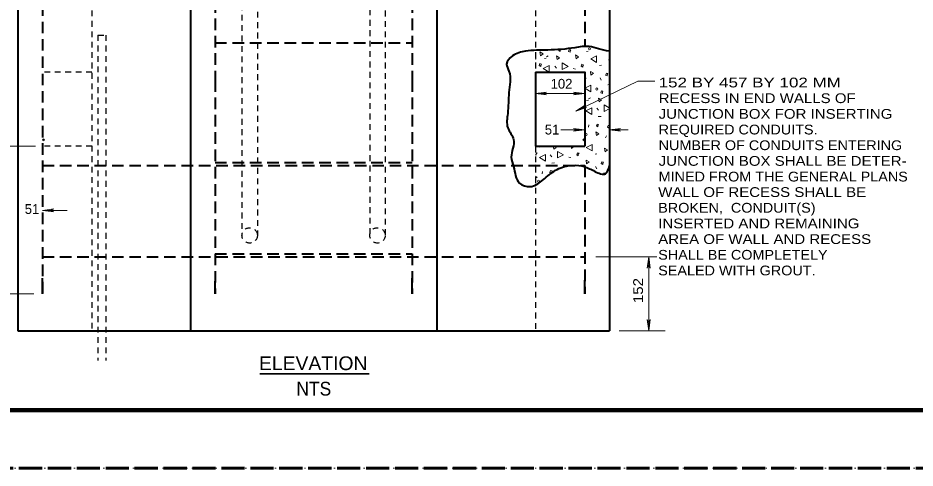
# Model space of a CAD drawing. Extents: x 312583 to 312854, y 144419 to 144597.
# Drawn here: x 312622.6 to 312692.4, y 144418.6 to 144453.6 of the extents above; entities that cross this region are included whole.
import ezdxf
from ezdxf.enums import TextEntityAlignment as Align

# ---------------------------------------------------------------- set-up
doc = ezdxf.new("R2010")
doc.units = 0
doc.header["$LTSCALE"] = 0.3
doc.header["$PDMODE"] = 32
doc.header["$PDSIZE"] = 0.15
for name, pattern in [('DOTTED', [1.5, 0.3, -1.2]), ('LONG_DASHED', [7.5, 6, -1.5]), ('MEDIUM_DASHED', [4.5, 3, -1.5]), ('SHORT_DASHED', [2.7, 1.5, -1.2])]:
    doc.linetypes.add(name, pattern=pattern)
doc.layers.add('1', color=7, linetype='Continuous', lineweight=13)
doc.layers.add('63', color=7, linetype='DOTTED', lineweight=13)

msp = doc.modelspace()

# ---------------------------------------------------------------- linework, layer by layer
at = {"layer": '1', "lineweight": 40}
for p, q in [((312622.6224, 144471.9161), (312622.6224, 144429.2664)), ((312636.039, 144471.9161), (312636.039, 144448.7628)), ((312655.2057, 144471.9161), (312655.2057, 144448.7628)), ((312668.6224, 144471.9161), (312668.6224, 144429.2664)), ((312662.8724, 144449.3914), (312662.8724, 144443.6414)), ((312636.039, 144448.7628), (312636.039, 144429.2664)), ((312655.2057, 144448.7628), (312655.2057, 144429.2664)), ((312662.8724, 144443.6414), (312666.7057, 144443.6414)), ((312624.539, 144432.1414), (312624.539, 144433.3604)), ((312637.9557, 144432.1414), (312637.9557, 144433.1381)), ((312653.289, 144432.1414), (312653.289, 144433.3604)), ((312666.7057, 144432.1414), (312666.7057, 144433.2148)), ((312622.6224, 144429.2664), (312668.6224, 144429.2664))]:
    msp.add_line(p, q, dxfattribs=at)
at = {"layer": '1', "linetype": 'SHORT_DASHED', "lineweight": 25}
for p, q in [((312628.3724, 144471.1954), (312628.3724, 144429.2664)), ((312662.8724, 144471.1954), (312662.8724, 144449.3914)), ((312640.0487, 144465.1924), (312640.0487, 144436.6878)), ((312641.2447, 144465.4224), (312641.2447, 144436.6878)), ((312649.9924, 144464.7938), (312649.9924, 144436.6878)), ((312651.1884, 144464.7094), (312651.1884, 144436.6878)), ((312628.8477, 144452.2664), (312628.8477, 144426.9664)), ((312628.8477, 144452.2664), (312629.4457, 144452.2664)), ((312629.4457, 144452.2664), (312629.4457, 144426.9664)), ((312628.3724, 144449.3914), (312624.539, 144449.3914)), ((312628.3724, 144443.6414), (312624.539, 144443.6414)), ((312662.8724, 144443.6414), (312662.8724, 144429.2664))]:
    msp.add_line(p, q, dxfattribs=at)
at = {"layer": '1', "linetype": 'MEDIUM_DASHED', "lineweight": 40}
for p, q in [((312624.539, 144469.5164), (312624.539, 144432.1414)), ((312637.9557, 144469.7541), (312637.9557, 144448.7628)), ((312653.289, 144469.7541), (312653.289, 144448.7628)), ((312666.7057, 144469.5164), (312666.7057, 144451.3541)), ((312637.9557, 144451.6838), (312653.289, 144451.6838)), ((312637.9557, 144448.7628), (312637.9557, 144432.1414)), ((312653.289, 144448.7628), (312653.289, 144432.1414)), ((312637.9557, 144442.3688), (312653.289, 144442.3688)), ((312624.539, 144442.1311), (312666.7057, 144442.1311)), ((312666.7057, 144442.1311), (312666.7057, 144432.1414)), ((312637.9557, 144435.2541), (312653.289, 144435.2541)), ((312624.539, 144435.0164), (312666.7057, 144435.0164))]:
    msp.add_line(p, q, dxfattribs=at)
at = {"layer": '1'}
for p, q in [((312663.7387, 144450.5874), (312663.869, 144450.6564)), ((312666.836, 144451.0091), (312666.9817, 144451.0168)), ((312662.857, 144450.4188), (312662.8954, 144450.3958)), ((312663.57, 144450.4571), (312663.7157, 144450.4878)), ((312664.375, 144449.8591), (312664.4977, 144449.6981)), ((312667.8557, 144449.9128), (312668.0014, 144449.9204)), ((312665.8087, 144449.6674), (312665.9774, 144449.6214)), ((312666.8284, 144448.9544), (312666.721, 144448.8701)), ((312667.894, 144448.9391), (312667.9784, 144448.7628)), ((312662.8724, 144447.7354), (312663.7387, 144447.8428)), ((312663.7387, 144447.8428), (312663.4627, 144447.7354)), ((312665.8394, 144447.8428), (312666.1154, 144447.7354)), ((312666.7057, 144447.7354), (312665.8394, 144447.8428)), ((312668.4997, 144448.4101), (312668.6147, 144448.4408)), ((312662.8724, 144447.7354), (312666.7057, 144447.7354)), ((312662.8724, 144447.7354), (312663.7387, 144447.6281)), ((312663.7387, 144447.6281), (312663.4627, 144447.7354)), ((312665.8394, 144447.6281), (312666.1154, 144447.7354)), ((312666.7057, 144447.7354), (312665.8394, 144447.6281)), ((312666.8437, 144447.1834), (312666.9894, 144447.2141)), ((312667.0124, 144447.3138), (312667.1427, 144447.3904)), ((312666.0234, 144446.3478), (312666.7517, 144446.8231)), ((312666.0234, 144446.3478), (312666.8514, 144446.6314)), ((312666.7517, 144446.8231), (312666.5524, 144446.6008)), ((312666.8514, 144446.6314), (312666.5524, 144446.6008)), ((312667.6487, 144446.5854), (312667.7714, 144446.4321)), ((312668.6147, 144446.6008), (312668.216, 144446.8461)), ((312667.7637, 144445.9338), (312667.9784, 144445.9414)), ((312665.8394, 144445.0138), (312666.1154, 144444.9064)), ((312666.7057, 144444.9064), (312665.8394, 144445.0138)), ((312667.0047, 144445.0981), (312667.0277, 144445.2898)), ((312668.607, 144445.1364), (312668.6147, 144445.1594)), ((312668.6224, 144444.9064), (312669.4887, 144445.0138)), ((312669.4887, 144445.0138), (312669.2127, 144444.9064)), ((312664.8552, 144444.9064), (312666.7057, 144444.9064)), ((312665.8394, 144444.7991), (312666.1154, 144444.9064)), ((312666.7057, 144444.9064), (312665.8394, 144444.7991)), ((312668.4, 144444.4388), (312668.3234, 144444.2701)), ((312668.6224, 144444.9064), (312670.079, 144444.9064)), ((312668.6224, 144444.9064), (312669.4887, 144444.7991)), ((312669.4887, 144444.7991), (312669.2127, 144444.9064)), ((312623.987, 144443.6414), (312617.434, 144443.6414)), ((312663.225, 144443.5648), (312663.3707, 144443.5954)), ((312664.2524, 144443.6414), (312664.2907, 144443.3884)), ((312665.6554, 144443.6261), (312665.6784, 144443.4498)), ((312664.03, 144442.9668), (312664.1527, 144442.8134)), ((312667.5107, 144443.0204), (312667.6564, 144443.0358)), ((312664.145, 144442.3151), (312664.3597, 144442.3228)), ((312665.4637, 144442.7751), (312665.6324, 144442.7368)), ((312663.386, 144441.4871), (312663.409, 144441.6711)), ((312664.122, 144441.5714), (312664.122, 144441.6174)), ((312667.549, 144442.0468), (312667.641, 144441.8781)), ((312668.1547, 144441.5178), (312668.3004, 144441.5638)), ((312624.5383, 144438.6357), (312625.4047, 144438.743)), ((312625.4047, 144438.743), (312625.1287, 144438.6357)), ((312624.5383, 144438.6357), (312626.4519, 144438.6357)), ((312624.5383, 144438.6357), (312625.4047, 144438.5283)), ((312625.4047, 144438.5283), (312625.1287, 144438.6357)), ((312667.572, 144435.0164), (312672.3254, 144435.0164)), ((312671.6814, 144435.0164), (312671.574, 144434.1501)), ((312671.6814, 144429.2664), (312671.6814, 144435.0164)), ((312671.6814, 144435.0164), (312671.7887, 144434.1501)), ((312671.574, 144434.1501), (312671.6814, 144434.4261)), ((312671.7887, 144434.1501), (312671.6814, 144434.4261)), ((312623.8567, 144432.1414), (312619.5864, 144432.1414)), ((312671.574, 144430.1328), (312671.6814, 144429.8568)), ((312671.6814, 144429.2664), (312671.574, 144430.1328)), ((312671.7887, 144430.1328), (312671.6814, 144429.8568)), ((312671.6814, 144429.2664), (312671.7887, 144430.1328)), ((312669.389, 144429.2664), (312672.9617, 144429.2664))]:
    msp.add_line(p, q, dxfattribs=at)
at = {"layer": '1', "lineweight": 35}
msp.add_line((312641.4323, 144425.9161), (312649.9363, 144425.9161), dxfattribs=at)
at = {"layer": '1', "lineweight": 158}
msp.add_line((312616.5, 144423.0846), (312849, 144423.0846), dxfattribs=at)
at = {"layer": '1', "linetype": 'LONG_DASHED', "lineweight": 60}
msp.add_line((312851.75, 144418.5846), (312583.526, 144418.5846), dxfattribs=at)
at = {"layer": '1'}
for points in [[(312662.8954, 144450.3958), (312662.8954, 144450.9094), (312662.857, 144450.8941)], [(312664.7277, 144451.1778), (312664.6817, 144451.0628), (312664.8044, 144450.9938), (312664.8044, 144451.1011)], [(312664.8044, 144451.1011), (312664.8504, 144451.1778), (312664.8197, 144451.1931)], [(312668.6224, 144450.3498), (312668.5917, 144450.3651), (312668.6224, 144450.1504)], [(312672.1644, 144448.6938), (312670.8304, 144448.6938), (312666.0234, 144446.3478)], [(312668.216, 144446.8461), (312668.216, 144446.3324), (312668.6147, 144446.5318)], [(312668.6147, 144445.2284), (312668.538, 144445.2514), (312668.4767, 144445.1058), (312668.607, 144445.0291), (312668.607, 144445.1364)], [(312664.2907, 144443.3884), (312664.4824, 144443.5341), (312664.306, 144443.6414)], [(312665.6784, 144443.4498), (312665.87, 144443.6031), (312665.8317, 144443.6261)], [(312662.9414, 144443.0434), (312662.995, 144443.1201), (312662.8724, 144443.1584), (312662.8724, 144443.1508)], [(312662.8724, 144442.9744), (312662.9414, 144442.9361), (312662.9414, 144443.0434)], [(312662.8724, 144442.1388), (312662.8954, 144442.1541), (312662.8724, 144442.1694)], [(312664.122, 144441.6174), (312664.168, 144441.7018), (312664.0454, 144441.7401), (312663.9917, 144441.5868), (312664.076, 144441.5408)], [(312662.8724, 144441.1344), (312663.0104, 144441.2034), (312662.8724, 144441.2878)]]:
    msp.add_lwpolyline(points, dxfattribs=at)
for points in [[(312663.271, 144450.6718), (312663.4627, 144450.8251), (312663.225, 144450.9631)], [(312664.5514, 144450.3651), (312664.743, 144450.5108), (312664.513, 144450.6488)], [(312665.571, 144451.0474), (312665.617, 144451.1241), (312665.502, 144451.1624), (312665.4407, 144451.0091), (312665.571, 144450.9401)], [(312666.031, 144450.4341), (312666.2227, 144450.5874), (312665.985, 144450.7254)], [(312667.6334, 144450.1428), (312667.6334, 144450.6641), (312667.1734, 144450.4264)], [(312663.2864, 144449.9281), (312663.3324, 144450.0124), (312663.2174, 144450.0508), (312663.156, 144449.8974), (312663.2864, 144449.8284)], [(312663.9457, 144449.3991), (312663.9457, 144449.9128), (312663.478, 144449.6828)], [(312664.9424, 144450.1198), (312664.9424, 144449.6061), (312665.41, 144449.8361)], [(312666.5524, 144449.8898), (312666.5984, 144449.9664), (312666.4834, 144450.0048), (312666.4297, 144449.8514), (312666.5524, 144449.7824)], [(312667.1887, 144449.1538), (312667.388, 144449.3071), (312667.1504, 144449.4451)], [(312668.4614, 144449.1998), (312668.5074, 144449.2764), (312668.3924, 144449.3148), (312668.331, 144449.1614), (312668.4614, 144449.0924)], [(312667.181, 144447.8581), (312667.181, 144448.3718), (312666.7134, 144448.1418)], [(312668.078, 144447.8274), (312668.124, 144447.9041), (312668.009, 144447.9424), (312667.9554, 144447.7891), (312668.078, 144447.7201)], [(312667.825, 144447.0914), (312668.0167, 144447.2371), (312667.779, 144447.3751)], [(312667.2654, 144446.0871), (312667.2654, 144446.6084), (312666.7977, 144446.3708)], [(312667.733, 144445.2361), (312667.779, 144445.3204), (312667.664, 144445.3511), (312667.6104, 144445.2054), (312667.733, 144445.1288)], [(312667.618, 144444.4541), (312667.8097, 144444.5998), (312667.5797, 144444.7378)], [(312667.296, 144443.2581), (312667.296, 144443.7718), (312666.8284, 144443.5341)], [(312663.6467, 144442.4761), (312663.6467, 144442.9898), (312663.179, 144442.7521)], [(312664.5974, 144443.2274), (312664.5974, 144442.7138), (312665.065, 144442.9438)], [(312666.2074, 144442.9974), (312666.261, 144443.0818), (312666.1384, 144443.1124), (312666.0847, 144442.9591), (312666.2074, 144442.8901)], [(312668.285, 144443.1891), (312668.4767, 144443.3348), (312668.2467, 144443.4804)], [(312666.8514, 144442.2691), (312667.043, 144442.4148), (312666.8054, 144442.5528)], [(312668.1164, 144442.3074), (312668.1624, 144442.3918), (312668.0474, 144442.4224), (312667.986, 144442.2768), (312668.1164, 144442.2001)]]:
    msp.add_lwpolyline(points, close=True, dxfattribs=at)
at = {"layer": '1', "lineweight": 40}
msp.add_lwpolyline([(312662.8724, 144449.3914), (312666.7057, 144449.3914), (312666.7057, 144443.6414)], dxfattribs=at)
at = {"layer": '1'}
for centre, radius in [((312667.0746, 144451.2129), 0.0784), ((312667.6475, 144448.0709), 0.0865), ((312666.8061, 144444.5305), 0.0784), ((312663.1131, 144440.9066), 0.0784)]:
    msp.add_circle(centre, radius, dxfattribs=at)
at = {"layer": '1', "linetype": 'SHORT_DASHED', "lineweight": 25}
for centre in [(312640.6467, 144436.6897), (312650.5904, 144436.6897)]:
    msp.add_circle(centre, 0.599, dxfattribs=at)
at = {"layer": '1', "lineweight": 40}
msp.add_spline([(312668.6224, 144451.0168), (312667.7714, 144451.2008), (312667.043, 144451.3848), (312665.939, 144451.2928), (312663.8307, 144451.1088), (312662.0904, 144451.0168), (312661.086, 144450.6488), (312660.626, 144450.0124), (312660.81, 144449.4604), (312660.81, 144447.8121), (312660.718, 144446.1638), (312660.718, 144445.0598), (312661.178, 144444.1474), (312660.994, 144442.7751), (312661.178, 144442.0391), (312661.6304, 144440.7588), (312662.4584, 144440.4828), (312663.3784, 144440.9351), (312664.2907, 144441.6711), (312664.8427, 144441.9471), (312666.675, 144442.0391), (312667.4954, 144441.6711), (312668.3234, 144441.4871), (312668.6224, 144442.1311)], degree=3, dxfattribs=at)
at = {"layer": '1'}
for p in [(312624.6004, 144444.1244), (312666.6367, 144444.1244)]:
    msp.add_point(p, dxfattribs=at)
at = {"layer": '63'}
msp.add_lwpolyline([(312601.2, 144418.5846), (312853.5, 144418.5846), (312853.5, 144596.7846)], dxfattribs=at)

# ---------------------------------------------------------------- texts
at = {"layer": '1'}
for s, p in [('102', (312664.0547, 144448.1055)), ('51 ', (312663.6, 144444.5382)), ('51 ', (312623.15, 144438.3601))]:
    msp.add_text(s, height=0.76, dxfattribs=at).set_placement(p)
for s, width, p in [('152 BY 457 BY 102 MM ', 1.3, (312672.4552, 144448.2031)), ('RECESS IN END WALLS OF', 1.15, (312672.4552, 144446.9831)), ('JUNCTION BOX FOR INSERTING ', 1.15, (312672.4552, 144445.7631)), ('REQUIRED CONDUITS. ', 1.1, (312672.4552, 144444.5431)), ('NUMBER OF CONDUITS ENTERING', 1.1, (312672.4552, 144443.3231)), ('JUNCTION BOX SHALL BE DETER-', 1.15, (312672.4552, 144442.1031)), ('MINED FROM THE GENERAL PLANS', 1.1, (312672.4552, 144440.8831)), ('WALL OF RECESS SHALL BE', 1.15, (312672.4228, 144439.6779)), ('BROKEN,  CONDUIT(S)', 1.1, (312672.4228, 144438.4579)), ('INSERTED AND REMAINING ', 1.15, (312672.4228, 144437.2379)), ('AREA OF WALL AND RECESS', 1.15, (312672.4228, 144436.0179)), ('SHALL BE COMPLETELY', 1.1, (312672.4228, 144434.7979)), ('SEALED WITH GROUT.', 1.1, (312672.4228, 144433.5779))]:
    msp.add_text(s, height=0.76, dxfattribs=dict(at, width=width)).set_placement(p)
at = {"layer": '1', "width": 1.15}
msp.add_text('152 ', height=0.76, rotation=90, dxfattribs=at).set_placement((312671.2376, 144431.4214))
at = {"layer": '1'}
for s, width, p in [('ELEVATION', 1.05, (312645.588, 144426.2052)), ('NTS', 0.95, (312645.6327, 144424.2255))]:
    msp.add_text(s, height=1.07, dxfattribs=dict(at, width=width)).set_placement(p, align=Align.CENTER)

doc.saveas('drawing.dxf')
